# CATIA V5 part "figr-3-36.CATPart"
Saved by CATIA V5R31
Part number: Part1
Bounding box of the stored display mesh (mm): x 0 to 71.72, y -62.404 to 71.526, z 0 to 0
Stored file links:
  D:\PROJECTS\Project 2021\US EDITION\CATIA V5 6R 2021\Resources\Part Files\c03_catia_v5_6r2021_prt\figr-3-36.CATPart
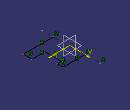
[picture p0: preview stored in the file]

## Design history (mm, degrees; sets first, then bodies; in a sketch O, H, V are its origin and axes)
Body1 (main body)
  Sketch1 on xy-plane, origin (0, 0, 0), H (1, 0, 0), V (0, 1, 0)
    axis line L1 (0, 71.5261) -> (1.8602, -62.4039)
    point P1 (0, 71.5261)
    line L2 (0.4896, 36.2738) -> (51.465, 36.2738)
    point P3 (0.4896, 36.2738)
    line L3 (51.465, 36.2738) -> (51.465, 23.0127)
    line L4 (51.465, 23.0127) -> (41.544, 23.0127)
    line L5 (41.544, 23.0127) -> (41.544, -16.3784)
    line L6 (41.544, -16.3784) -> (71.7203, -16.3784)
    line L7 (71.7203, -16.3784) -> (71.7203, -36.696)
    line L8 (71.7203, -36.696) -> (1.5031, -36.696)
    point P10 (1.5031, -36.696)
    coincidence: P1 V, P3 L1, P10 L1
    horizontal: L2 H, L4 H, L6 H, L8 H
    vertical: L3 V, L5 V, L7 V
